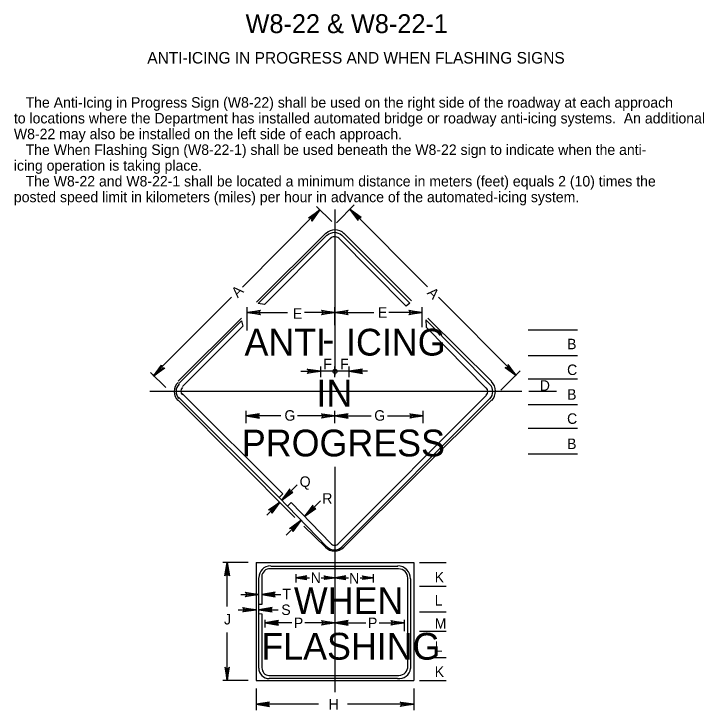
# Model space of a CAD drawing. Extents: x 0.012 to 0.196, y 0.004 to 0.259.
# Drawn here: x 0.027 to 0.1912, y 0.0936 to 0.2593 of the extents above; entities that cross this region are included whole.
import ezdxf

# ---------------------------------------------------------------- set-up
doc = ezdxf.new("R2010")
doc.units = 0
for name, color, linetype in [('1', 7, 'Continuous'), ('11', 7, 'Continuous'), ('12', 7, 'Continuous'), ('2', 7, 'Continuous'), ('3', 7, 'Continuous')]:
    doc.layers.add(name, color=color, linetype=linetype)

# ---------------------------------------------------------------- blocks, each defined once
blk = doc.blocks.new('RARROW')
at = {"layer": '3'}
for p, q in [((-2.156, 0.28500000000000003), (-2.2665, 0.384625)), ((-2.2665, 0.384625), (0, 0)), ((0, 0), (-2.2665, -0.379125)), ((-2.156, 0.28500000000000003), (-2.075625, 0.12075)), ((0, 0), (-2.156, 0.28500000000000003)), ((-2.14975, -0.2705), (0, 0)), ((-2.075625, 0.12075), (0, 0)), ((0, 0), (-2.074, -0.108)), ((-2.2665, -0.379125), (-2.14975, -0.2705)), ((-2.074, -0.108), (-2.14975, -0.2705))]:
    blk.add_line(p, q, dxfattribs=at)

msp = doc.modelspace()

# ---------------------------------------------------------------- linework, layer by layer
at = {"layer": '1'}
for p, q in [((0.09440823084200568, 0.14726681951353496), (0.09073101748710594, 0.1436061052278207)), ((0.090125, 0.14425), (0.092125, 0.142125)), ((0.09025816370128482, 0.14313312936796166), (0.08715267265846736, 0.14004156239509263)), ((0.09995093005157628, 0.14343432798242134), (0.09620714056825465, 0.13970733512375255)), ((0.09533241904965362, 0.13883204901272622), (0.09176349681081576, 0.13527912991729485)), ((0.08525, 0.116625), (0.08525, 0.11875000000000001))]:
    msp.add_line(p, q, dxfattribs=at)
msp.add_circle((0.10340009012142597, 0.17424899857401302), 0.0004877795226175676, dxfattribs=at)
at = {"layer": '11'}
for p, q in [((0.08475, 0.19075), (0.10125, 0.207125)), ((0.1055, 0.207125), (0.121625, 0.191)), ((0.085125, 0.19037500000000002), (0.1015, 0.206625)), ((0.10237500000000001, 0.20600000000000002), (0.08662500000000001, 0.19012500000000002)), ((0.10225000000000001, 0.205875), (0.10237500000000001, 0.20600000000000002)), ((0.120375, 0.18975), (0.10425, 0.20600000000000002)), ((0.105, 0.206625), (0.12125, 0.1905)), ((0.08662500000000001, 0.19012500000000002), (0.085125, 0.19037500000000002)), ((0.12125, 0.1905), (0.120375, 0.18975)), ((0.066125, 0.171875), (0.081125, 0.186875)), ((0.06625, 0.171375), (0.081125, 0.18625)), ((0.081125, 0.18625), (0.0815, 0.185)), ((0.14025, 0.171125), (0.125, 0.1865)), ((0.125, 0.1865), (0.12512500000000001, 0.18475)), ((0.1255, 0.186875), (0.140625, 0.171875)), ((0.0815, 0.185), (0.067125, 0.170625)), ((0.12512500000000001, 0.18475), (0.139375, 0.17025)), ((0.093875, 0.1395), (0.066125, 0.167375)), ((0.090125, 0.14425), (0.06625, 0.168)), ((0.067125, 0.168875), (0.091, 0.145125)), ((0.139375, 0.1685), (0.10425, 0.13325)), ((0.105, 0.1325), (0.14025, 0.16775)), ((0.140625, 0.167375), (0.1055, 0.132375)), ((0.091, 0.145125), (0.090125, 0.14425)), ((0.093, 0.14300000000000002), (0.092125, 0.142125)), ((0.10237500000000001, 0.13325), (0.093, 0.14300000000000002)), ((0.092125, 0.142125), (0.1015, 0.1325)), ((0.101125, 0.132375), (0.096, 0.137375)), ((0.088125, 0.12787500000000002), (0.11837500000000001, 0.12787500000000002)), ((0.11850000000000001, 0.12725), (0.088, 0.12725)), ((0.08525, 0.11875000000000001), (0.08525, 0.12512500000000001)), ((0.12075, 0.104125), (0.12075, 0.125)), ((0.121375, 0.124875), (0.121375, 0.10350000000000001)), ((0.08775000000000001, 0.10187500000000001), (0.11862500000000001, 0.10187500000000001)), ((0.11825000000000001, 0.101125), (0.08775000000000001, 0.101125))]:
    msp.add_line(p, q, dxfattribs=at)
for points in [[(0.08600000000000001, 0.12537500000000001), (0.08600000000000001, 0.11875000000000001), (0.08525, 0.11875000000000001)], [(0.08525, 0.10362500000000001), (0.08525, 0.116625), (0.08600000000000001, 0.1165), (0.08600000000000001, 0.10362500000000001)]]:
    msp.add_lwpolyline(points, dxfattribs=at)
for centre, radius, start, end in [((0.10341658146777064, 0.2049392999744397), 0.0030032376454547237, 44.96247777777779, 135.03752500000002), ((0.10330135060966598, 0.20481699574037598), 0.0024649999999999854, 44.91796944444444, 135), ((0.10335402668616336, 0.20487489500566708), 0.0014163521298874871, 48.551211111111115, 138.60145555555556), ((0.06818795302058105, 0.16943647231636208), 0.0030600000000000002, 134.16918611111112, 224.9628638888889), ((0.06806348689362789, 0.1694728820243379), 0.0024649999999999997, 135, 223.34960833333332), ((0.13850564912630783, 0.16942422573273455), 0.002445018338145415, 315.96693055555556, 44.95301666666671), ((0.138388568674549, 0.1695488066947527), 0.0032107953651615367, 315.82084444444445, 44.80693055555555), ((0.06802184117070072, 0.16952040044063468), 0.0012749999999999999, 135, 225), ((0.13850564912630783, 0.16942422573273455), 0.0012550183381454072, 315.96693055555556, 44.95301666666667), ((0.10331250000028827, 0.13414685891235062), 0.0012974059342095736, 223.73079444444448, 316.2692083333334), ((0.10331250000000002, 0.13446767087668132), 0.00302728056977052, 223.73079166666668, 316.2692055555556), ((0.1032618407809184, 0.13413572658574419), 0.0023867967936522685, 224.2005777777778, 316.7389916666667), ((0.08806223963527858, 0.1251420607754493), 0.0027865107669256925, 89.98362500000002, 179.98362500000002), ((0.11834103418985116, 0.1248895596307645), 0.0030340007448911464, 359.7250472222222, 89.72504722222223), ((0.08790592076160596, 0.12531663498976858), 0.0019356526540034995, 87.21413333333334, 177.21413333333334), ((0.11850434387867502, 0.1250122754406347), 0.0022186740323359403, 0, 90), ((0.08775685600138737, 0.10359593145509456), 0.002481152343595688, 179.74110000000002, 269.7411), ((0.08774091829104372, 0.10360761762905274), 0.0017155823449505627, 178.22643333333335, 268.2264333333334), ((0.11863925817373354, 0.10388925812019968), 0.0027915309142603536, 261.9844111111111, 351.9844111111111), ((0.11855871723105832, 0.1040765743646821), 0.0022025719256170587, 271.72448333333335, 1.7244833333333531)]:
    msp.add_arc(centre, radius, start, end, dxfattribs=at)
at = {"layer": '3'}
for p, q in [((0.10375000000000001, 0.209625), (0.108, 0.213875)), ((0.08141658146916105, 0.19431151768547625), (0.09972929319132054, 0.21274880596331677)), ((0.10262500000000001, 0.209875), (0.099, 0.2135)), ((0.10337500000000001, 0.21275), (0.10337500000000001, 0.173375)), ((0.12537500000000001, 0.194375), (0.107, 0.212875)), ((0.07875, 0.19187500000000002), (0.06025, 0.173375)), ((0.128, 0.19187500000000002), (0.1465, 0.173375)), ((0.0825, 0.184), (0.0825, 0.1895)), ((0.10337500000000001, 0.18525), (0.10337500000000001, 0.1895)), ((0.124125, 0.18475), (0.124125, 0.1895)), ((0.0825, 0.18825), (0.092125, 0.18825)), ((0.10337500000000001, 0.18825), (0.096125, 0.18825)), ((0.10337500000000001, 0.18825), (0.112625, 0.18825)), ((0.124125, 0.18825), (0.11625, 0.18825)), ((0.149375, 0.184125), (0.161125, 0.184125)), ((0.149375, 0.178), (0.161125, 0.178)), ((0.063125, 0.170375), (0.059500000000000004, 0.17400000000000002)), ((0.09525, 0.17425000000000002), (0.1, 0.17425000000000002)), ((0.1, 0.172875), (0.1, 0.175375)), ((0.10675, 0.17425000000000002), (0.1, 0.17425000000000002)), ((0.10337500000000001, 0.172875), (0.10337500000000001, 0.175375)), ((0.10675, 0.172875), (0.10675, 0.175375)), ((0.111125, 0.17425000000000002), (0.10675, 0.17425000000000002)), ((0.142875, 0.16975), (0.1475, 0.174375)), ((0.149375, 0.17250000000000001), (0.161125, 0.17250000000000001)), ((0.059375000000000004, 0.1695), (0.147875, 0.1695)), ((0.1495, 0.1695), (0.156125, 0.1695)), ((0.149375, 0.166375), (0.161125, 0.166375)), ((0.08225, 0.161875), (0.08225, 0.164875)), ((0.10337500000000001, 0.161875), (0.10337500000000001, 0.164875)), ((0.124375, 0.161875), (0.124375, 0.164875)), ((0.0905, 0.163625), (0.08225, 0.163625)), ((0.10337500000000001, 0.163625), (0.0945, 0.163625)), ((0.10337500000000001, 0.163625), (0.112, 0.163625)), ((0.115875, 0.163625), (0.124375, 0.163625)), ((0.149375, 0.16075), (0.161125, 0.16075)), ((0.149375, 0.154625), (0.161125, 0.154625)), ((0.10337500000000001, 0.1515), (0.10337500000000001, 0.13)), ((0.10337500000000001, 0.13), (0.10337500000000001, 0.097875)), ((0.08275, 0.12875), (0.07675, 0.12875)), ((0.07775, 0.11825000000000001), (0.07775, 0.12875)), ((0.084625, 0.12875), (0.084625, 0.100625)), ((0.084625, 0.12875), (0.122125, 0.12875)), ((0.122125, 0.12875), (0.122125, 0.100625)), ((0.1235, 0.12875), (0.129875, 0.12875)), ((0.094125, 0.126), (0.094125, 0.124)), ((0.1125, 0.126), (0.1125, 0.124)), ((0.094125, 0.12512500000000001), (0.097375, 0.12512500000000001)), ((0.100125, 0.12512500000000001), (0.10337500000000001, 0.12512500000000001)), ((0.10337500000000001, 0.12512500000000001), (0.106625, 0.12512500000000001)), ((0.109375, 0.12512500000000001), (0.1125, 0.12512500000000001)), ((0.1235, 0.123125), (0.129875, 0.123125)), ((0.081, 0.121125), (0.08525, 0.121125)), ((0.08600000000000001, 0.121125), (0.0905, 0.121125)), ((0.080375, 0.11750000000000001), (0.084625, 0.11750000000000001)), ((0.08525, 0.11750000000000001), (0.089875, 0.11750000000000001)), ((0.1235, 0.117), (0.129875, 0.117)), ((0.08675000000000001, 0.115125), (0.08675000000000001, 0.11325)), ((0.093125, 0.114375), (0.08675000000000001, 0.114375)), ((0.10337500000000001, 0.114375), (0.09625, 0.114375)), ((0.10337500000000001, 0.114375), (0.11075, 0.114375)), ((0.113875, 0.114375), (0.11987500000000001, 0.114375)), ((0.11987500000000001, 0.115125), (0.11987500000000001, 0.112375)), ((0.07775, 0.100625), (0.07775, 0.112125)), ((0.1235, 0.112375), (0.129875, 0.112375)), ((0.1235, 0.106125), (0.129875, 0.106125)), ((0.08275, 0.100625), (0.07675, 0.100625)), ((0.084625, 0.100625), (0.122125, 0.100625)), ((0.1235, 0.100625), (0.129875, 0.100625)), ((0.084625, 0.09875), (0.084625, 0.093625)), ((0.122125, 0.09875), (0.122125, 0.093625)), ((0.0995, 0.095), (0.084625, 0.095)), ((0.122125, 0.095), (0.106375, 0.095))]:
    msp.add_line(p, q, dxfattribs=at)

# ---------------------------------------------------------------- block references
for p, xscale, yscale, rotation in [((0.09975, 0.212625), 0.0014063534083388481, 0.0013911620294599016, 45), ((0.107, 0.21275), 0.0014063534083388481, -0.0013911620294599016, 135), ((0.0825, 0.18825), 0.0014063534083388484, 0.001391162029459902, 180), ((0.10337500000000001, 0.18825), 0.0014063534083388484, 0.001391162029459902, 180), ((0.06025, 0.173125), 0.0014063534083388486, 0.0013911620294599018, -135), ((0.1465, 0.17325000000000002), 0.0014063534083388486, -0.0013911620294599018, -45), ((0.10675, 0.17425000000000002), 0.0014063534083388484, -0.001391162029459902, 180), ((0.08225, 0.163625), 0.0014063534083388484, -0.001391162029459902, 180), ((0.10337500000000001, 0.163625), 0.0014063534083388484, -0.001391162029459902, 180), ((0.09075, 0.143625), 0.0014063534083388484, -0.0013911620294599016, -135), ((0.09025, 0.143125), 0.0014063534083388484, 0.0013911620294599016, 44.99999999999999), ((0.09625, 0.13975), 0.0014063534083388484, -0.0013911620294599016, -135), ((0.09525, 0.13875), 0.0014063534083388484, 0.0013911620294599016, 44.99999999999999), ((0.07775, 0.12875), 0.0014063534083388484, 0.001391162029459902, 90), ((0.094125, 0.12512500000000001), 0.0011391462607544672, -0.0011268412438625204, 180), ((0.10337500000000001, 0.12512500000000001), 0.0011391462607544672, -0.0011268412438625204, 180), ((0.08600000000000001, 0.121125), 0.0014063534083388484, -0.001391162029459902, 180), ((0.08525, 0.11750000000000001), 0.0014063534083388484, -0.001391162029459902, 180), ((0.08675000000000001, 0.114375), 0.0014063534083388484, -0.001391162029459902, 180), ((0.10337500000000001, 0.114375), 0.0014063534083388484, -0.001391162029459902, 180), ((0.07775, 0.100625), 0.0014063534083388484, -0.001391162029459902, -90.00000000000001), ((0.084625, 0.095), 0.0014063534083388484, -0.001391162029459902, 180)]:
    msp.add_blockref('RARROW', p, dxfattribs=dict(at, xscale=xscale, yscale=yscale, rotation=rotation))
for p, xscale, yscale in [((0.10337500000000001, 0.18825), 0.0014063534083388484, 0.001391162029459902), ((0.124125, 0.18825), 0.0014063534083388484, 0.001391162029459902), ((0.1, 0.17425000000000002), 0.0014063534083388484, 0.001391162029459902), ((0.10337500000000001, 0.163625), 0.0014063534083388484, 0.001391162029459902), ((0.124375, 0.163625), 0.0014063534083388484, 0.001391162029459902), ((0.10337500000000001, 0.12512500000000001), 0.0011391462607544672, 0.0011268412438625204), ((0.1125, 0.12512500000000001), 0.0011391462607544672, 0.0011268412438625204), ((0.08525, 0.121125), 0.0014063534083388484, 0.001391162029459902), ((0.084625, 0.11750000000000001), 0.0014063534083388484, 0.001391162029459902), ((0.10337500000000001, 0.114375), 0.0014063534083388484, 0.001391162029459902), ((0.11987500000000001, 0.114375), 0.0014063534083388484, 0.001391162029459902), ((0.122125, 0.095), 0.0014063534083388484, 0.001391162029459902)]:
    msp.add_blockref('RARROW', p, dxfattribs=dict(at, xscale=xscale, yscale=yscale))

# ---------------------------------------------------------------- texts
at = {"layer": '1'}
for s, height, p in [('W8-22 & W8-22-1', 0.0045000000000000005, (0.082125, 0.25475000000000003)), ('ANTI-ICING IN PROGRESS AND WHEN FLASHING SIGNS', 0.00275025, (0.058750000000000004, 0.2475))]:
    msp.add_text(s, height=height, dxfattribs=at).set_placement(p)
at = {"layer": '12'}
for s, p in [('ANTI  ICING', (0.081875, 0.178)), ('IN', (0.099, 0.165875)), ('PROGRESS', (0.08125, 0.154)), ('WHEN', (0.093625, 0.1165)), ('FLASHING', (0.085875, 0.105625))]:
    msp.add_text(s, height=0.0063750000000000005, dxfattribs=at).set_placement(p)
at = {"layer": '2'}
for s, p in [('   The Anti-Icing in Progress Sign (W8-22) shall be used on the right side of the roadway at each approach', (0.027, 0.23700000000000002)), ('to locations where the Department has installed automated bridge or roadway anti-icing systems.  An additional ', (0.027, 0.23325)), ('W8-22 may also be installed on the left side of each approach.', (0.027, 0.2295)), ('   The When Flashing Sign (W8-22-1) shall be used beneath the W8-22 sign to indicate when the anti-', (0.027, 0.22575)), ('icing operation is taking place.', (0.027, 0.222)), ('   The W8-22 and W8-22-1 shall be located a minimum distance in meters (feet) equals 2 (10) times the ', (0.027, 0.21825)), ('posted speed limit in kilometers (miles) per hour in advance of the automated-icing system.', (0.027, 0.2145))]:
    msp.add_text(s, height=0.0024997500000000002, dxfattribs=at).set_placement(p)
at = {"layer": '3'}
for rotation, p in [(45, (0.08025, 0.19162500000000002)), (315, (0.12512500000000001, 0.19275))]:
    msp.add_text('A', height=0.0024997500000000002, rotation=rotation, dxfattribs=at).set_placement(p)
for s, height, p in [('E', 0.0024997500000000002, (0.093375, 0.18675)), ('E', 0.0024997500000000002, (0.113625, 0.187)), ('-', 0.0063750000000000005, (0.100375, 0.17875)), ('B', 0.0024997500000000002, (0.15862500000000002, 0.1795)), ('F', 0.0024997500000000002, (0.100625, 0.17475000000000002)), ('F', 0.0024997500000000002, (0.104625, 0.17475000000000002)), ('C', 0.0024997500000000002, (0.15862500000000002, 0.173375)), ('D', 0.0024997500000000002, (0.152125, 0.169625)), ('B', 0.0024997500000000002, (0.15862500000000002, 0.1675)), ('G', 0.0024997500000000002, (0.091375, 0.1625)), ('G', 0.0024997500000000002, (0.11275, 0.1625)), ('C', 0.0024997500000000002, (0.15862500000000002, 0.16175)), ('B', 0.0024997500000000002, (0.15862500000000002, 0.15575)), ('Q', 0.0024997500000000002, (0.095, 0.14675)), ('R', 0.0024997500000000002, (0.100375, 0.14275000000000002)), ('N', 0.0024997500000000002, (0.097625, 0.123875)), ('N', 0.0024997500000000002, (0.10675, 0.12375)), ('K', 0.0024997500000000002, (0.12712500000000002, 0.124)), ('T', 0.0024997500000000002, (0.090875, 0.12)), ('L', 0.0024997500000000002, (0.12712500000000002, 0.11850000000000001)), ('S', 0.0024997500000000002, (0.090625, 0.11625)), ('J', 0.0024997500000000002, (0.077, 0.114)), ('P', 0.0024997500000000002, (0.093625, 0.113125)), ('P', 0.0024997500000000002, (0.11125, 0.113125)), ('M', 0.0024997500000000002, (0.12712500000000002, 0.113)), ('L', 0.0024997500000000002, (0.12712500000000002, 0.1075)), ('K', 0.0024997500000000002, (0.12712500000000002, 0.1015)), ('H', 0.0024997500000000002, (0.10187500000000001, 0.09375))]:
    msp.add_text(s, height=height, dxfattribs=at).set_placement(p)

doc.saveas('drawing.dxf')
